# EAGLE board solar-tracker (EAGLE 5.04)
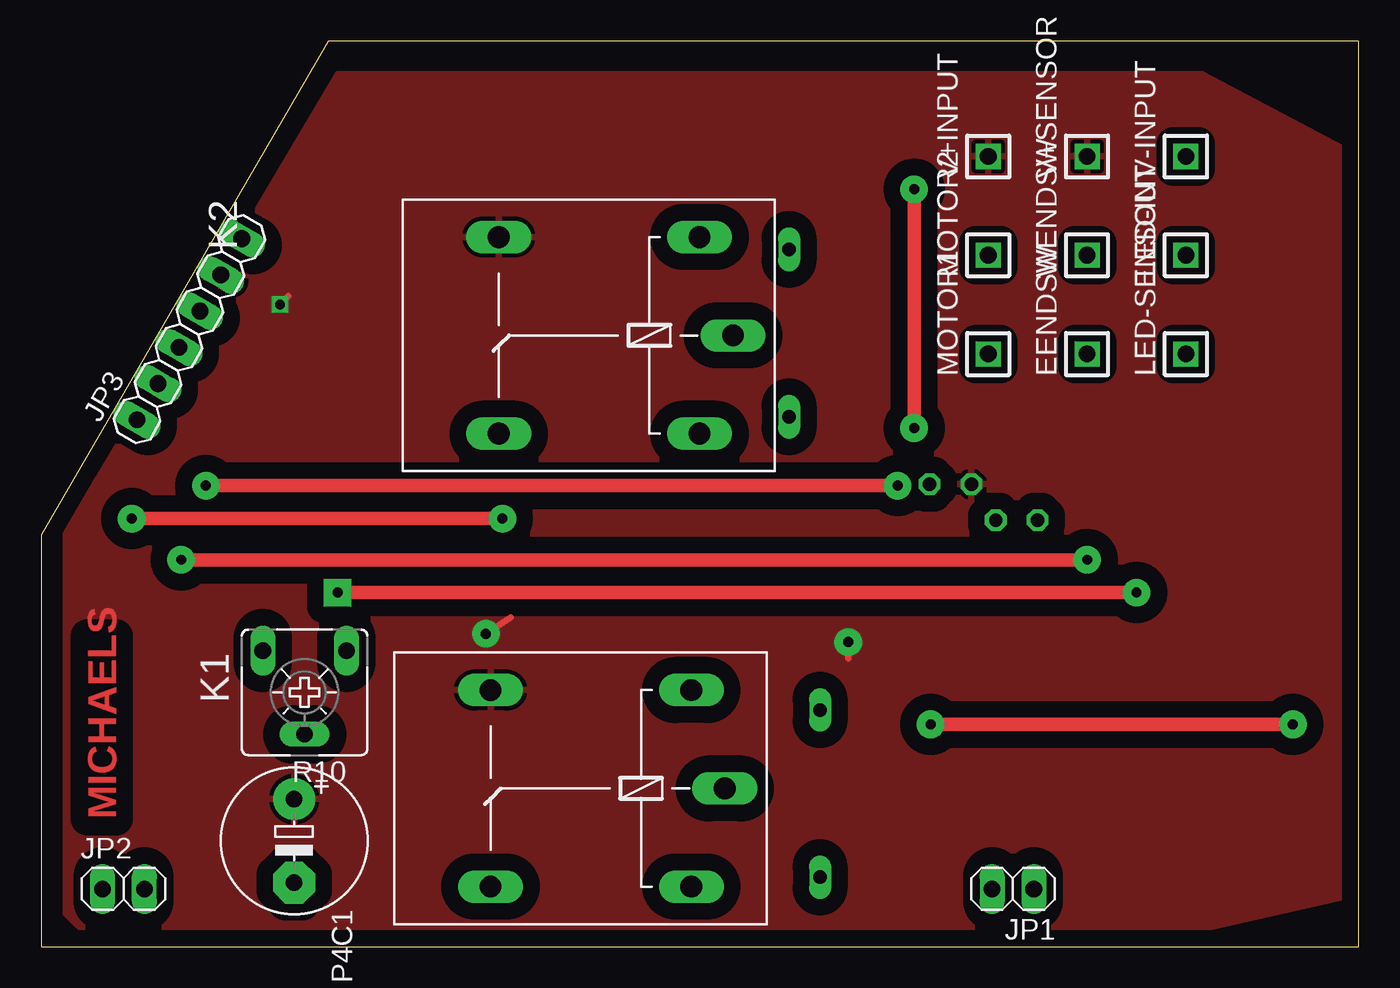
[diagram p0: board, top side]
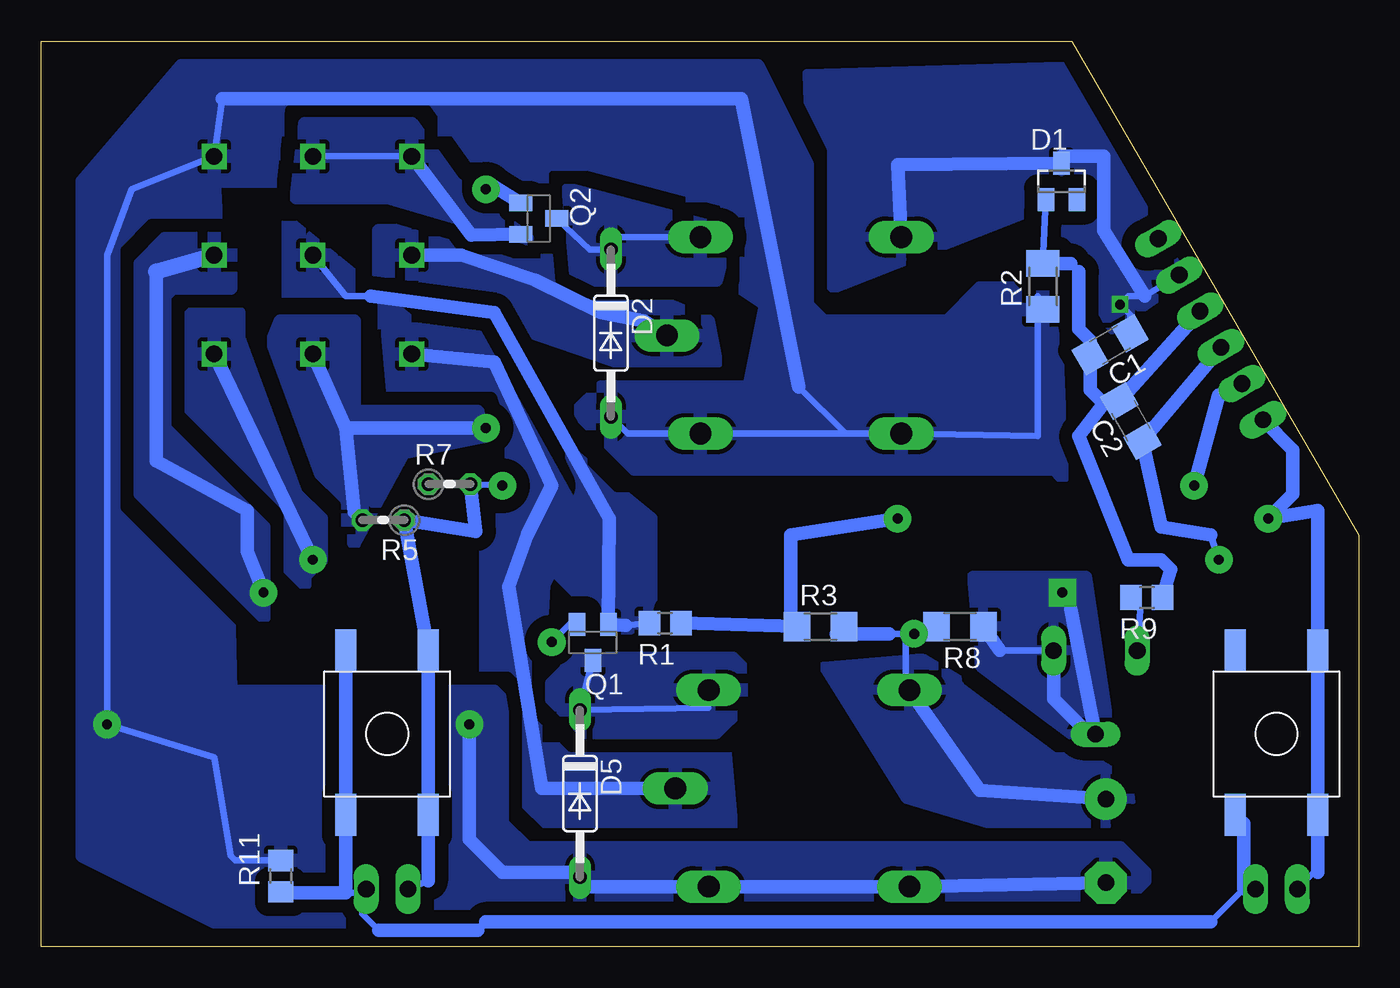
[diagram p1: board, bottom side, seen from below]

Size 80 x 55 mm. Coordinates in mm from the lower left corner, seen from the top.
Outline: 0,0 80,0 80,55 17.43,55 0,25 0,0
Copper layers (1*16): Top 0.035mm / dielectric 1.5mm / Bottom 0.035mm
Design rules "default *": minimum track width 40mil, minimum drill 30mil, track to track 8mil, track to pad 8mil, pad to pad 8mil, via to via 8mil, smd to smd 8mil, copper to edge 40mil, drill to drill 8mil, minimum pad ring 10mil, minimum via ring 8mil, stop-mask expansion 4mil, vias tented up to drill 0mil, thermal gap 10mil

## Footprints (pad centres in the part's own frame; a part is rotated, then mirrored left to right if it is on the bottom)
C1206 = smd 1.6 x 1.8: 1 -1.4,0; 2 1.4,0
SOT23 = smd 1 x 1.4: 1 -0.95,-1.1; 2 0.95,-1.1; 3 0,1.1
DO35-10 = drill 0.813 long: A 5.08,0; C -5.08,0
1X01 = drill 1.016 square: 1 0,0
1X02 = drill 1.016 long: 1 -1.27,0; 2 1.27,0
1X06 = drill 1.016 long: 1 -6.35,0; 2 -3.81,0; 3 -1.27,0; 4 1.27,0; 5 3.81,0; 6 6.35,0
G5LE = drill 1.321 long: 1 -7.493,-5.969; 2 -7.493,5.969; O 4.699,5.969; P -9.525,0; S 4.699,-5.969
E5-8,5 = drill 1.016 pad 2.54 round: + -2.54,0 | drill 1.016 pad 2.54 octagon: - 2.54,0
SOT23-BEC = smd 1 x 1.4: B -0.95,-1.1; C 0,1.1; E 0.95,-1.1
R0805 = smd 1.3 x 1.5: 1 -0.95,0; 2 0.95,0
M1206 = smd 1.6 x 2: 1 -1.4,0; 2 1.4,0
R1206 = smd 1.6 x 1.803: 1 -1.422,0; 2 1.422,0
0204V = drill 0.813 octagon: 1 -1.27,0; 2 1.27,0
CA6V = drill 1.016 long: A -2.54,-2.54; E 2.54,-2.54; S 0,2.54
SMD10/5 = smd 1.27 x 2.54: P$1 -2.5,0; P$2 2.5,0; P$3 2.5,10; P$4 -2.5,10

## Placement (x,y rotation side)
C1  [C1206]  15.1,36.56 210 bottom
C2  [C1206]  13.84,31.93 120 bottom
D1  [SOT23]  18.05,46.48 0 bottom
D2  1N4148DO35-10  [DO35-10]  45.41,37.27 270 bottom
D5  1N4148DO35-10  [DO35-10]  47.29,9.29 270 bottom
EENDSW  [1X01]  63.5,36 90 top
JP1  [1X02]  59,3.5 180 top
JP2  [1X02]  5,3.5 0 top
JP3  [1X06]  9,37.5 60 top
K1  G5LE  [G5LE]  31.98,9.61 180 top
K2  G5LE  [G5LE]  32.48,37.13 180 top
LED-IN  [1X01]  69.5,42 90 top
LED-SENSOUT  [1X01]  69.5,36 90 top
MOTOR1  [1X01]  57.5,36 90 top
MOTOR2  [1X01]  57.5,42 90 top
P4C1  47u 10  [E5-8,5]  15.36,6.42 270 top
Q1  BC327SMD  [SOT23-BEC]  46.51,18.47 180 bottom
Q2  BC327SMD  [SOT23-BEC]  49.79,44.23 270 bottom
R1  [R0805]  42.11,19.65 180 bottom
R2  [M1206]  19.18,40.11 90 bottom
R3  [R1206]  32.69,19.44 0 bottom
R5  [0204V]  59.23,25.9 180 bottom
R7  [0204V]  55.21,28.09 0 bottom
R8  [R1206]  24.21,19.44 180 bottom
R9  [R0805]  12.87,21.21 180 bottom
R10  [CA6V]  15.99,15.44 180 top
R11  [R0805]  65.45,4.28 90 bottom
U$1  SMDBUT  [SMD10/5]  59,18 180 bottom
U$2  SMDBUT  [SMD10/5]  5,18 180 bottom
V+INPUT  [1X01]  57.5,48 90 top
V+SENSOR  [1X01]  63.5,48 90 top
V-INPUT  [1X01]  69.5,48 90 top
WENDSW  [1X01]  63.5,42 90 top

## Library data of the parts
C1 C2 R1-R3 R5 R7-R9 R11 = rcl-2
D1 D2 D5 = diode-1
EENDSW LED-IN LED-SENSOUT MOTOR1 MOTOR2 V+INPUT V+SENSOR V-INPUT WENDSW = pinhead(2)
JP1-JP3 = pinhead
K1 K2 = relay
P4C1 = rcl
Q1 Q2 = transistor-pnp
R10 = pot
U$1 U$2 = switch-omron

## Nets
MOTO1: K2.P MOTOR2.1
MOTO2: K1.P MOTOR1.1
N$1: R9.2 R10.E
N$3: LED-IN.1 R8.1 R10.A R10.S
N$5: C1.2 C2.2 D1.1 JP3.4 R2.2 R9.1
N$6: JP1.1 JP2.2 R11.1 U$1.P$2 U$2.P$3
N$7: C2.1 JP3.3 LED-SENSOUT.1
N$8: Q1.B R1.2 WENDSW.1
N$11: D5.C K1.1 Q1.C
N$13: JP2.1 JP3.1 R1.1 R3.1 U$2.P$4
N$14: JP1.2 JP3.2 R5.1 R7.2 U$1.P$1
N$15: EENDSW.1 Q2.B R5.2
Q1-C: D2.C K2.1 Q2.C
V+: C1.1 D1.3 JP3.5 K1.S K2.S P4C1.+ Q1.E Q2.E R3.2 R7.1 R8.2 V+INPUT.1 V+SENSOR.1
V-: D2.A D5.A K1.2 K1.O K2.2 K2.O P4C1.- R2.1 R11.2 V-INPUT.1

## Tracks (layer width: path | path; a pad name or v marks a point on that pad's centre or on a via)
MOTO1
  Bottom 0.813: MOTOR2.1 54.5,42 50,40.5 46,38.5 43.38,38 K2.P
  pour Bottom (isolate 0.813, rank 3): 39.5,38 53,43.5 59.5,43.5 59.5,40.5 43.5,35 39,35.5
MOTO2
  Bottom 0.813: K1.P 49.61,9.61 51.61,21.89 50.5,25 49,28 52.5,35.5 MOTOR1.1
  pour Bottom (isolate 0.813, rank 4): 38.5,12 50,12 49.5,22 47.5,26 51.5,37.5 59,37.5 58.5,32 53,31.5 53,6.5 38,6.5
N$1
  Bottom 0.406: R10.E 13.28,20.43 R9.2
N$3  (via drill 0.6 pad 1.68)
  Top 0.813: v18,21.5 v66.5,21.5
  Bottom 0.406: 17.5,20.5 v18,21.5 | 16.5,13 16.09,13 R10.S | R10.A 21.8,17.98
  Bottom 0.813: v66.5,21.5 67.5,24 67.5,26.5 73,29.5 73,41 | R10.S 17.5,20.5 | R10.A 18.54,15.04 16.5,13 | 21.8,17.98 R8.1
  Bottom 1.016: 73,41 LED-IN.1
  pour Bottom (isolate 0.813, rank 3): 15,12.5 16.5,22.5 23.5,22.5 23,17 17,12.5
  pour Bottom (isolate 0.813): 68.5,43 72.5,43 74,41.5 74,27.5 66.5,20 66.5,25.5 67.5,26.5 72.5,31.5 72.5,39.5 72,40 68.5,40
N$5
  Bottom 0.406: D1.1 R2.2 19.5,41.18 19.5,41 19,41.5 | 15.5,33 14.67,33 C2.2 | C1.2 16.31,36.81 | 17,41 17.5,41.5
  Bottom 0.813: C2.2 JP3.4 | R9.1 11.42,22.92 12,23.5 14,23.5 17,31 15.5,33 16.31,33.81 C1.2 | 16.31,36.81 17,37.5 17,41 | 17.5,41.5 19,41.5
N$6
  Bottom 0.406: JP2.2 7,3.5 9,1.5 | 53,1.5 53.5,1 | 59.5,1 60.5,2 60.5,3.27 | 60.5,3.27 JP1.1 | 60.5,3.27 61.5,3.27 | 65.39,3.27 R11.1 | 7,7.5 U$2.P$3
  Bottom 0.813: 9,1.5 53,1.5 | 53.5,1 59.5,1 | 65.39,3.27 61.5,3.27 U$1.P$2 | 7,3.5 7,7.5
N$7  (via drill 0.6 pad 1.68)
  Top 0.813: v8.5,23.5 v63.5,23.5
  Bottom 0.406: v8.5,23.5 9,25
  Bottom 0.813: v63.5,23.5 LED-SENSOUT.1 | JP3.3 C2.1 12,25.5 9,25
  pour Bottom (isolate 0.813, rank 2): 68,38.5 71.5,38.5 72,38 72,30.5 71,29.5 71,29 64,22 64,22.5 63,23.5 63,26 64.5,27.5 68,37
N$8
  Bottom 0.406: WENDSW.1 61.5,39.5 60,39.5 | R1.2 44.5,19.5
  Bottom 0.813: 60,39.5 52.5,38.5 45.5,26 Q1.B 44.5,19.5
  pour Bottom (isolate 1.016, rank 4): 43,20 43,26 65,44 65,39 62,39.5 48.5,22.5 45,19
N$11
  Bottom 0.406: Q1.C D5.C 39.5,14.5 K1.1
  pour Bottom (isolate 0.61, rank 2): 37.5,16 37.5,14.5 39,13 47,13 49,15 49,16 47.5,17.5 38,17.5 37.5,17
N$13  (via drill 0.6 pad 1.68)
  Top 0.406: v5.5,26 6,26
  Top 0.813: 6,26 v28,26
  Bottom 0.406: 34.5,19.94 R3.1 | 2.5,4.5 2.73,4.5 JP2.1
  Bottom 0.813: JP3.1 4,30.18 4,27.5 v5.5,26 2.5,26.5 U$2.P$4 2.5,4.5 | R3.1 R1.1 | 34.5,19.94 34.5,25 v28,26
N$14  (via drill 0.6 pad 1.68)
  Top 0.813: v10,28 v52,28
  Bottom 0.406: 56.5,4 JP1.2 | v52,28 R7.2 | 8.5,33.5 JP3.2
  Bottom 0.813: 56.5,4 U$1.P$1 R5.1 53.6,25.23 R7.2 | v10,28 8.5,33.5
N$15  (via drill 0.6 pad 1.68)
  Top 0.813: v53,31.5 v53,46
  Bottom 0.406: v53,46 52.5,46.17 | 61,26.4 R5.2
  Bottom 0.813: 52.5,46.17 Q2.B | v53,31.5 61.5,31.5 | 61.5,31.5 EENDSW.1 | 61.5,31.5 61,26.4
  pour Bottom (isolate 0.813, rank 3): 61,38 65.5,38 66.5,35.5 61,24.5 58,30 53,31 53.5,32.5 61,32.5
Q1-C
  Bottom 0.406: K2.1 45.41,43.1 D2.C 46.69,42.34 Q2.C
  pour Bottom (isolate 0.813): 38.5,43.5 48,46 47.5,40.5 39,40.5 38.5,42.5
V+  (via drill 0.6, 0.6 pad 1.68)
  Top 0.406: v49,18.5 49,17.5 | v14.5,39 15,39.5 | v27,19 28.5,20
  Bottom 0.406: K1.S 27.5,15.58 27.5,19 28.5,19 v27,19 26.44,19.44 R8.2 | 31.74,19 R3.2 | V+INPUT.1 V+SENSOR.1 | JP3.5 13,39.5 14,39.5 v14.5,39 13.89,38.39 C1.1 | 18,48 D1.3 | Q1.E 47.93,19.57 v49,18.5
  Bottom 0.813: 28.5,19 31.74,19 | V+INPUT.1 53.89,43.21 Q2.E | 13,39.5 15.5,43.5 15.5,48 18,48 | D1.3 28,47.5 K2.S | P4C1.+ 23,9.5 K1.S
  pour Top (isolate 1.016, rank 5): 18,53 70.5,53 79,48.5 79,3 68,0.5 3,0.5 1.5,2 1.5,26.5 3.5,28.5
  pour Bottom (isolate 0.61): 50.5,43 55,46.5 57.5,50 64,50 64.5,45.5 59,45.5
  pour Bottom (isolate 0.813, rank 4): 14,10 26.5,17.5 32.5,17 27.5,9 17.5,6 13.5,6
  pour Bottom (isolate 0.813, rank 4): 10,41 16,53.5 33.5,53 33,39.5 19,45 15,37.5
V-  (via drill 0.6 pad 1.68)
  Top 0.813: v54,13.5 v76,13.5
  Bottom 0.406: 46.72,3.64 D5.A 47.58,4.5 | K2.O K2.2 44.39,31.16 D2.A | K2.O 31.16,31.16 34,34 | R11.2 68.23,5.23 68.5,5.5 69.5,11.5 v76,13.5 76,42 74.5,46 V-INPUT.1 69,51.5 | K2.O 19.5,31 19.5,39.5 R2.1
  Bottom 0.813: 46.72,3.64 K1.2 K1.O P4C1.- | 34,34 37.5,51.5 69,51.5 | v54,13.5 54,6.5 52,4.5 47.58,4.5
  pour Bottom (isolate 0.813, rank 2): 18.5,40 23,40 25,38 32.5,38 33.5,39 33.5,47.5 36.5,53.5 71.5,53.5 77.5,46.5 77.5,5.5 69.5,1.5 15.5,1.5 13,4 13,4.5 14.5,6 50.5,6 52,7.5 52,15 52.5,15.5 68.5,15.5 69,37.5 69.5,46.5 43.5,46.5 37.5,40 36,39 37,34 46,34 47.5,32.5 44,29 18.5,29 18,28.5

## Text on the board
Top: MICHAELS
